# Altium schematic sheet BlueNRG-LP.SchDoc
size 297 x 209 mm
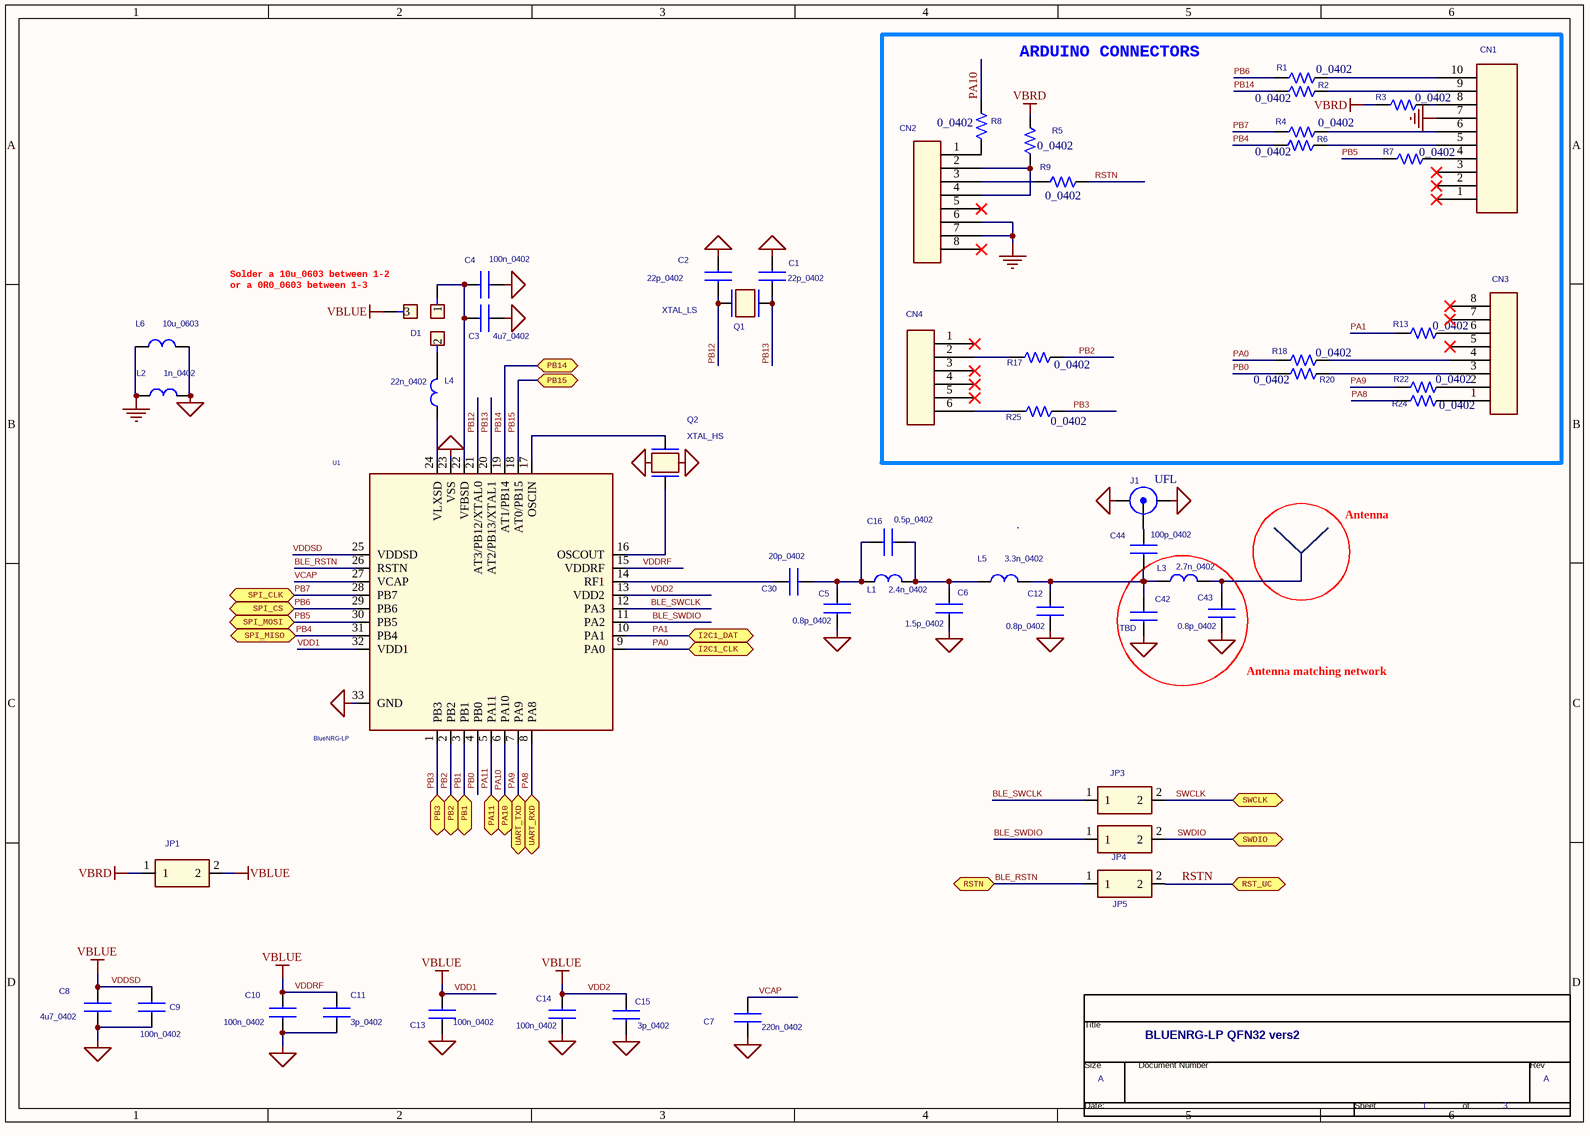
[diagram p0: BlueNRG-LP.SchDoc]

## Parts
*  Page Count: 3  Page Number: 1  Page Size: A  Title: BLUENRG-LP QFN32 vers2  (hidden comment: TitleBlock0)  (graphical)
C1  22p_0402  [0402_CAP_NP]
C2  22p_0402  [0402_CAP_NP]
C3  4u7_0402  [0402_CAP_NP]
C4  100n_0402  [0402_CAP_NP]
C5  0.8p_0402  [0402_CAP_NP]
C6  1.5p_0402  [0402_CAP_NP]
C7  220n_0402  [0402_CAP_NP]
C8  4u7_0402  [0402_CAP_NP]
C9  100n_0402  [0402_CAP_NP]
C10  100n_0402  [0402_CAP_NP]
C11  3p_0402  [0402_CAP_NP]
C12  0.8p_0402  [0402_CAP_NP]
C13  100n_0402  [0402_CAP_NP]
C14  100n_0402  [0402_CAP_NP]
C15  3p_0402  [0402_CAP_NP]
C16  0.5p_0402  [0402_CAP_NP]
C30  20p_0402  [0402_CAP_NP]
C42  TBD  [0402_CAP_NP]
C43  0.8p_0402  [0402_CAP_NP]
C44  100p_0402  [0402_CAP_NP]
CN1  CON10  [HDR1X10]  (value not drawn)
CN2  CON8  [HDR1X8]  (value not drawn)
CN3  CON8  [HDR1X8]  (value not drawn)
CN4  CON6  [HDR1X6]  (value not drawn)
D1  DEV3L  [DEV3L0603]  (value not drawn)
J1  UFL  [UFL_SMT]
JP1  JUMPER 2  [HDR 2 X 1 M]  (value not drawn)
JP3  JUMPER 2  [HDR 2 X 1 M]  (value not drawn)
JP4  JUMPER 2  [HDR 2 X 1 M]  (value not drawn)
JP5  JUMPER 2  [HDR 2 X 1 M]  (value not drawn)
L1  2.4n_0402  [0402-A]
L2  1n_0402  [0402-A]
L3  2.7n_0402  [0402-A]
L4  22n_0402  [0402-A]
L5  3.3n_0402  [0402-A]
L6  10u_0603  [0603_CAP_NP]
Q1  XTAL_LS  [NX2012SA]
Q2  XTAL_HS  [NX2016SA]
R1  0_0402  [0402_RESISTOR]
R2  0_0402  [0402_RESISTOR]
R3  0_0402  [0402_RESISTOR]
R4  0_0402  [0402_RESISTOR]
R5  0_0402  [0402_RESISTOR]
R6  0_0402  [0402_RESISTOR]
R7  0_0402  [0402_RESISTOR]
R8  0_0402  [0402_RESISTOR]
R9  0_0402  [0402_RESISTOR]
R13  0_0402  [0402_RESISTOR]
R17  0_0402  [0402_RESISTOR]
R18  0_0402  [0402_RESISTOR]
R20  0_0402  [0402_RESISTOR]
R22  0_0402  [0402_RESISTOR]
R24  0_0402  [0402_RESISTOR]
R25  0_0402  [0402_RESISTOR]
U1  BlueNRG-LP  [QFN32]

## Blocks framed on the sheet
ARDUINO CONNECTORS: CN1-CN4 R1-R9 R13 R17 R18 R20 R22 R24 R25

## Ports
I2C1_CLK (bidir), I2C1_DAT (bidir), PA10 (bidir), PA11 (bidir), PB1 (bidir), PB2 (bidir), PB3 (bidir), PB14 (bidir), PB15 (bidir), RST_UC (bidir), RSTN (bidir), SPI_CLK (bidir), SPI_CS (bidir), SPI_MISO (bidir), SPI_MOSI (bidir), SWCLK (bidir), SWDIO (bidir), UART_RXD (bidir), UART_TXD (bidir)

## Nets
GND: CN1.7 CN2.6 CN2.7 L2.1 L6.1
GND_RF: C1.1 C2.1 C3.1 C4.1 C5.1 C6.1 C7.1 C8.1 C9.1 C10.1 C11.1 C12.1 C13.1 C14.1 C15.1 C42.1 C43.1 J1.1 J1.3 L2.2 L6.2 Q2.2 Q2.4(gnd1) U1.23(VSS) U1.33(GND)
VBRD: JP1.1 R3.1 R5.2
VDD1: C8.2 C9.2 C10.2 C11.2 C13.2 C14.2 C15.2 D1.3 JP1.2 U1.13(VDD2) U1.15(VDDRF) U1.25(VDDSD) U1.32(VDD1)  [also labelled VBLUE, VDD2, VDDRF, VDDSD]
BLE_RSTN: JP5.1 U1.26(RSTN) ; port RSTN
BLE_SWCLK: JP3.1 U1.12(PA3)
BLE_SWDIO: JP4.1 U1.11(PA2)
PA0: R18.1 U1.9(PA0) ; port I2C1_CLK
PA1: R13.1 U1.10(PA1) ; port I2C1_DAT
PA8: R24.1 U1.8(PA8) ; port UART_RXD
PA9: R22.1 U1.7(PA9) ; port UART_TXD
PA10: R8.2 U1.6(PA10) ; port PA10
PA11: U1.5(PA11) ; port PA11
PB0: R20.1 U1.4(PB0)
PB1: U1.3(PB1) ; port PB1
PB2: R17.2 U1.2(PB2) ; port PB2
PB3: R25.2 U1.1(PB3) ; port PB3
PB4: R6.1 U1.31(PB4) ; port SPI_MISO
PB5: R7.1 U1.30(PB5) ; port SPI_MOSI
PB6: R1.1 U1.29(PB6) ; port SPI_CS
PB7: R4.1 U1.28(PB7) ; port SPI_CLK
PB12: C2.2 Q1.1 U1.21(AT3/PB12/XTAL0)
PB13: C1.2 Q1.2 U1.20(AT2/PB13/XTAL1)
PB14: R2.1 U1.19(AT1/PB14) ; port PB14
PB15: U1.18(AT0/PB15) ; port PB15
RSTN: JP5.2 R9.2 ; port RST_UC
SWCLK: JP3.2 ; port SWCLK
SWDIO: JP4.2 ; port SWDIO
VCAP: C7.2 U1.27(VCAP)
NetC3_2: C3.2 C4.2 D1.1 U1.22(VFBSD)
NetC5_2: C5.2 C16.2 C30.1 L1.1
NetC6_2: C6.2 C16.1 L1.2 L5.1
NetC12_2: C12.2 C42.2 C44.1 L3.1 L5.2
NetC30_2: C30.2 U1.14(RF1)
NetC43_2: C43.2 L3.2
NetC44_2: C44.2 J1.2
NetCN1_4: CN1.4 R7.2
NetCN1_5: CN1.5 R6.2
NetCN1_6: CN1.6 R4.2
NetCN1_8: CN1.8 R3.2
NetCN1_9: CN1.9 R2.2
NetCN1_10: CN1.10 R1.2
NetCN2_1: CN2.1 R8.1
NetCN2_2: CN2.2 CN2.4 R5.1
NetCN2_3: CN2.3 R9.1
NetCN3_1: CN3.1 R24.2
NetCN3_2: CN3.2 R22.2
NetCN3_3: CN3.3 R20.2
NetCN3_4: CN3.4 R18.2
NetCN3_6: CN3.6 R13.2
NetCN4_2: CN4.2 R17.1
NetCN4_6: CN4.6 R25.1
NetD1_2: D1.2 L4.2
NetL4_1: L4.1 U1.24(VLXSD)
NetQ2_1: Q2.1 U1.17(OSCIN)
NetQ2_3: Q2.3 U1.16(OSCOUT)

Not connected (* = marked no-connect by the designer): CN1 1* 2* 3*; CN2 5* 8*; CN3 5* 7* 8*; CN4 1* 3* 4* 5*

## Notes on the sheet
- (near D1) Solder a 10u_0603 between 1-2
  or a 0R0_0603 between 1-3
- Antenna
- (near C43) Antenna matching network

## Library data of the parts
* = TitleBlock0: Doc: BLUENRG-248 APPLICATION BOARD
C1 C6 C10 C12 C13 C15 = MURATA GRM36: COMPSIDE: TOP; COMPLOC: [-1955.000,605.000]; COMPROT: 180; COMPGROUP: 0; COMPFIXED: NO; COMPHEIGHT: 0.000
C2-C5 C7-C9 C11 C14 C16 C30 C42-C44 = MURATA GRM36: COMPHEIGHT: 0.000; MEMORY: NO; COMPGROUP: 0; COMPROT: 180; COMPLOC: [-1955.000,605.000]; COMPSIDE: TOP
D1 = DEV3L_0
J1 = UFL: 50 Ohms, SMA Jack Receptacle, Edge Mount, .25µm Gold (Au) Plating; Manufacturer: Molex; Manufacturer’s ordering code / Orderable Part Number: 73251-1150; STEVAL: FKIxxx; Value: SMA_RF
JP1 JP3-JP5 = Buzzer
L1-L6 = IND_short
Q1 = QUARZO
Q2 = NX3225SA: COMPSIDE: TOP; COMPLOC: [-2158.000,974.000]; COMPROT: 180; COMPGROUP: 0; COMPFIXED: NO; COMPHEIGHT: 0.000
R1-R9 R13 R17 R18 R20 R22 R24 R25 = R_Dup1: PSpiceTemplate: R^@REFDES %1 %2 ?TOLERANCE¦R^@REFDES¦ @VALUE  ?TOLERANCE¦\n.model R^@REFDES RES R=1 DEV=@TOLERANCE%¦
U1 = BlueNRG-LP_0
